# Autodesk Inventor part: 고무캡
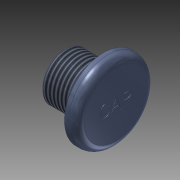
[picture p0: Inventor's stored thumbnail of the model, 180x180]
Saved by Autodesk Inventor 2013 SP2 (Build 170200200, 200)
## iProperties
Created: 2017-06
Part Number: 고무캡
Material: 고무
Document SubType Name: Modeling
Designer: mduedu
Density: 1 g/cm^3
Author: mduedu
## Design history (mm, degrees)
sketch "스케치1"
  geometry: L1 (0, 0)-(13, 0); L2 (13, 0)-(13, 10); L3 (13, 10)-(10, 10); L4 (0, 6)-(0, 0); L5 (0, 6)-(8, 6); L6 (8, 6)-(8, 8); L7 (8, 8)-(10, 8); L8 (10, 8)-(10, 10)
  constraints: 16 end point, 2 horizontal, 2 parallel, 2 perpendicular, 2 point on line, 1 vertical
  dimensions: "d0" = 20 diameter of L3 L1; "d2" = 12 diameter of L5 L1; "d6" = 5 distance between parallel lines of L2 L6; "d8" = 16 diameter of L7 L1; "d9" = 8 distance between parallel lines of L6 L4; "d32" = 2 distance of L6.end L7.end
revolve "회전1" sketch "스케치1" stored, may be unused: angle "d10" = 90 deg
hole "구멍1" diameter "d22" = 5; stored, may be unused: countersink angle "d26" = 90 deg, drill point angle "d28" = 0 deg; dims "d23" = 6, "d24" = 4, "d25" = 2, "d27" = 6, "d30" = 10, "d31" = 10
chamfer "모따기1" distance "d13" = 0.5; stored, may be unused: second distance "d14" = 2, angle "d15" = 45 deg
fillet "모깎기3" dims "d29" = 1
fillet "모깎기2" dims "d17" = 2
sketch "스케치3"
  geometry: 2 further points
  constraints: 1 coincident, 1 other
feature "엠보싱1" sketch "스케치3" dims "d18" = 0.2, "d19" = 0, "d29" = 1
feature "스레드1" dims "d33" = 10, "d34" = 0
node "솔리드1"
